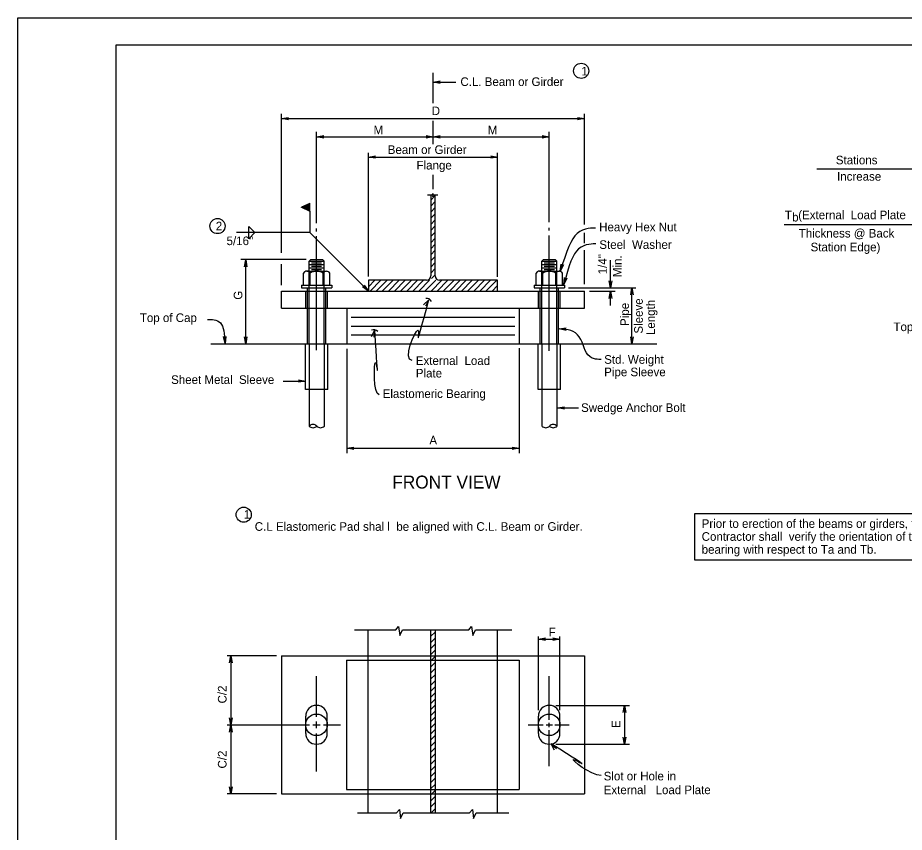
# Model space of a CAD drawing. Extents: x 113 to 232, y -103 to -27.
# Drawn here: x 115.25 to 123.82, y -54.27 to -46.39 of the extents above; entities that cross this region are included whole.
import ezdxf

# ---------------------------------------------------------------- set-up
doc = ezdxf.new("R2010")
doc.units = 0
for name, color, linetype in [('1', 7, 'Continuous'), ('B_Border', 7, 'Continuous'), ('B_Dimension', 7, 'Continuous'), ('B_No_Plot', 7, 'Continuous')]:
    doc.layers.add(name, color=color, linetype=linetype)

msp = doc.modelspace()

# ---------------------------------------------------------------- linework, layer by layer
at = {"layer": '1'}
for p, q in [((119.2638, -47.219), (119.2638, -46.9267)), ((119.2638, -47.0179), (119.4812, -47.0179)), ((117.7967, -48.6674), (117.7967, -47.3251)), ((117.7967, -47.3697), (120.7267, -47.3697)), ((119.2638, -47.6169), (119.2638, -47.3899)), ((120.7267, -48.3947), (120.7267, -47.3251)), ((118.1367, -48.3815), (118.1367, -47.4974)), ((118.1367, -47.5465), (119.2638, -47.5465)), ((119.2638, -47.5465), (120.3867, -47.5465)), ((120.3867, -48.3708), (120.3867, -47.4965)), ((118.6367, -48.8964), (118.6367, -47.7017)), ((118.6367, -47.7412), (119.8881, -47.7412)), ((119.8867, -48.8988), (119.8867, -47.7017)), ((119.2638, -48.0528), (119.2638, -47.9124)), ((122.9723, -47.8557), (124.0302, -47.8557)), ((119.21, -48.1072), (119.2535, -48.1072)), ((119.2409, -48.1072), (119.2409, -48.8915)), ((119.2535, -48.1072), (119.2614, -48.0931)), ((119.2614, -48.0931), (119.2614, -48.1262)), ((119.2614, -48.1262), (119.2676, -48.1072)), ((119.2676, -48.1072), (119.3079, -48.1072)), ((119.2824, -48.8915), (119.2824, -48.1072)), ((118.0711, -48.1895), (117.9901, -48.2273)), ((117.9901, -48.2273), (118.0711, -48.265)), ((118.0711, -48.1895), (118.0711, -48.1889)), ((118.0711, -48.265), (118.0711, -48.1895)), ((118.0711, -48.265), (118.0711, -48.2955)), ((118.0711, -48.2955), (118.0711, -48.4717)), ((117.4812, -48.5307), (117.4812, -48.4127)), ((117.4812, -48.4127), (117.5402, -48.4717)), ((118.1367, -48.46), (118.1367, -48.4325)), ((120.3867, -48.4531), (120.3867, -48.4257)), ((122.6575, -48.3931), (124.0554, -48.3931)), ((118.0711, -48.4717), (117.3619, -48.4717)), ((117.5402, -48.4717), (117.4812, -48.5307)), ((118.6367, -49.0373), (118.0711, -48.4717)), ((118.1367, -49.6095), (118.1367, -48.5071)), ((120.3867, -49.6144), (120.3867, -48.5002)), ((120.7267, -48.5731), (120.7267, -48.4734)), ((120.7267, -48.97), (120.7267, -48.6414)), ((118.0361, -48.7319), (117.4048, -48.7319)), ((117.4509, -49.5478), (117.4509, -48.7355)), ((117.7967, -48.9818), (117.7967, -48.7758)), ((118.0801, -48.7319), (118.0637, -48.7482)), ((118.0637, -48.8454), (118.0637, -48.7482)), ((118.0637, -48.7482), (118.2096, -48.7482)), ((118.0801, -48.7319), (118.1932, -48.7319)), ((118.0881, -48.7645), (118.1852, -48.7645)), ((118.1932, -48.7319), (118.2096, -48.7482)), ((118.2096, -48.8454), (118.2096, -48.7482)), ((120.3137, -48.7482), (120.3301, -48.7319)), ((120.3137, -48.7482), (120.4596, -48.7482)), ((120.3137, -48.8454), (120.3137, -48.7482)), ((120.3137, -48.7482), (120.4596, -48.7482)), ((120.3301, -48.7319), (120.4432, -48.7319)), ((120.3381, -48.7645), (120.4352, -48.7645)), ((120.4432, -48.7319), (120.4596, -48.7482)), ((120.4596, -48.8454), (120.4596, -48.7482)), ((120.978, -49.0064), (120.978, -48.7374)), ((118.0414, -48.8454), (118.2322, -48.8454)), ((118.0637, -48.7806), (118.2096, -48.7806)), ((118.0637, -48.813), (118.2096, -48.813)), ((118.0637, -49.5478), (118.0637, -48.8454)), ((118.0881, -48.797), (118.1852, -48.797)), ((118.0881, -48.8293), (118.1852, -48.8293)), ((118.2096, -49.5478), (118.2096, -48.8454)), ((120.2914, -48.8454), (120.4822, -48.8454)), ((120.3137, -48.7806), (120.4596, -48.7806)), ((120.3137, -48.813), (120.4596, -48.813)), ((120.3137, -49.5478), (120.3137, -48.8454)), ((120.3381, -48.797), (120.4352, -48.797)), ((120.3381, -48.8293), (120.4352, -48.8293)), ((120.4596, -49.5478), (120.4596, -48.8454)), ((118.0093, -48.9792), (118.0093, -48.8637)), ((118.0737, -48.9792), (118.0737, -48.8637)), ((118.1998, -48.9792), (118.1998, -48.8637)), ((118.2644, -48.9792), (118.2644, -48.8637)), ((119.1992, -48.9331), (118.6367, -48.9331)), ((118.6367, -48.9331), (118.6367, -49.0373)), ((119.8867, -48.9331), (119.3241, -48.9331)), ((119.8867, -49.0373), (119.8867, -48.9331)), ((120.2593, -48.9792), (120.2593, -48.8637)), ((120.3237, -48.9792), (120.3237, -48.8637)), ((120.4498, -48.9792), (120.4498, -48.8637)), ((120.5144, -48.9792), (120.5144, -48.8637)), ((117.9908, -48.9792), (118.2825, -48.9792)), ((117.9908, -48.9792), (117.9908, -49.0052)), ((117.9908, -49.0052), (118.2825, -49.0052)), ((118.0482, -49.0385), (118.0482, -49.0055)), ((118.2252, -49.0385), (118.2252, -49.0055)), ((118.2825, -48.9792), (118.2825, -49.0052)), ((120.2408, -48.9792), (120.5325, -48.9792)), ((120.2408, -48.9792), (120.2408, -49.0052)), ((120.2408, -49.0052), (120.5325, -49.0052)), ((120.2982, -49.0381), (120.2982, -49.0048)), ((120.4752, -49.0381), (120.4752, -49.0058)), ((120.5325, -48.9792), (120.5325, -49.0052)), ((120.5724, -49.0052), (121.2237, -49.0052)), ((121.1859, -49.5478), (121.1859, -49.0052)), ((117.7967, -49.204), (117.7967, -49.0373)), ((117.7967, -49.0373), (120.7267, -49.0373)), ((118.0326, -49.204), (118.0326, -49.0385)), ((118.0482, -49.204), (118.0482, -49.0385)), ((118.2252, -49.2038), (118.2252, -49.0385)), ((118.2407, -49.204), (118.2407, -49.0385)), ((120.2826, -49.2049), (120.2826, -49.0381)), ((120.2982, -49.2049), (120.2982, -49.0381)), ((120.4752, -49.2059), (120.4752, -49.0411)), ((120.4907, -49.2059), (120.4907, -49.0411)), ((120.7267, -49.204), (120.7267, -49.0373)), ((120.7745, -49.0373), (121.0236, -49.0373)), ((120.978, -49.1773), (120.978, -49.0397)), ((117.7967, -49.204), (120.7267, -49.204)), ((118.0482, -49.5478), (118.0482, -49.204)), ((118.2252, -49.5478), (118.2252, -49.2038)), ((118.4283, -49.204), (118.4283, -49.5478)), ((120.095, -49.204), (120.095, -49.5478)), ((118.47, -49.29), (120.0533, -49.29)), ((120.2982, -49.5478), (120.2982, -49.2049)), ((120.4752, -49.5478), (120.4752, -49.2059)), ((118.47, -49.376), (120.0533, -49.376)), ((118.47, -49.4619), (120.0533, -49.4619)), ((117.1126, -49.5478), (121.4253, -49.5478)), ((118.0282, -49.988), (118.0282, -49.5478)), ((118.0637, -49.5478), (118.0637, -49.988)), ((118.2096, -49.5478), (118.2096, -49.988)), ((118.2452, -49.988), (118.2452, -49.5478)), ((118.4283, -49.5953), (118.4283, -50.6057)), ((120.095, -49.5908), (120.095, -50.6057)), ((120.2782, -49.988), (120.2782, -49.5478)), ((120.3137, -49.5478), (120.3137, -49.988)), ((120.4596, -49.5478), (120.4596, -49.988)), ((120.4952, -49.988), (120.4952, -49.5478)), ((117.8138, -49.9073), (118.0297, -49.9073)), ((118.2452, -49.988), (118.0282, -49.988)), ((118.0637, -49.988), (118.0637, -50.3446)), ((118.2096, -49.988), (118.2096, -50.3445)), ((120.4952, -49.988), (120.2782, -49.988)), ((120.3137, -49.988), (120.3137, -50.3411)), ((120.4596, -49.988), (120.4596, -50.3413)), ((120.4665, -50.1678), (120.6692, -50.1678)), ((118.4283, -50.558), (120.095, -50.558)), ((118.502, -52.3141), (118.9014, -52.3141)), ((118.6354, -54.0829), (118.6354, -52.3141)), ((118.966, -52.3141), (119.6076, -52.3141)), ((119.2396, -54.0829), (119.2396, -52.3141)), ((119.2812, -52.3141), (119.2812, -54.0829)), ((119.6722, -52.3141), (120.0232, -52.3141)), ((119.8854, -54.0829), (119.8854, -52.3141)), ((120.2812, -53.0901), (120.2812, -52.3775)), ((120.2812, -52.4036), (120.4896, -52.4036)), ((120.4896, -53.0901), (120.4896, -52.3775)), ((117.7475, -52.5653), (117.2701, -52.5653)), ((117.3072, -52.5653), (117.3072, -53.2335)), ((117.7954, -52.5653), (117.7954, -53.8986)), ((117.7954, -52.5653), (118.6328, -52.5653)), ((118.427, -52.607), (118.427, -53.857)), ((118.427, -52.607), (120.0938, -52.607)), ((118.6328, -52.5653), (119.8877, -52.5653)), ((119.8877, -52.5653), (120.7254, -52.5653)), ((120.0938, -52.607), (120.0938, -53.857)), ((120.7254, -52.5653), (120.7254, -53.8986)), ((118.1354, -53.1561), (118.1354, -52.7613)), ((120.3854, -53.184), (120.3854, -52.7613)), ((120.4492, -53.0445), (121.1627, -53.0445)), ((121.1142, -53.0445), (121.1142, -53.4195)), ((117.2701, -53.232), (118.068, -53.232)), ((117.3072, -53.2335), (117.3072, -53.8986)), ((118.0312, -53.3153), (118.0312, -53.1486)), ((118.0993, -53.232), (118.1707, -53.232)), ((118.1354, -53.2648), (118.1354, -53.2014)), ((118.2019, -53.232), (118.2396, -53.232)), ((118.2396, -53.3153), (118.2396, -53.1486)), ((118.2396, -53.232), (118.3665, -53.232)), ((120.1817, -53.232), (120.3258, -53.232)), ((120.2812, -53.3153), (120.2812, -53.1486)), ((120.3571, -53.232), (120.4162, -53.232)), ((120.3854, -53.2535), (120.3854, -53.2118)), ((120.4406, -53.232), (120.4896, -53.232)), ((120.4896, -53.3153), (120.4896, -53.1486)), ((120.4896, -53.232), (120.5795, -53.232)), ((118.1354, -53.6818), (118.1354, -53.316)), ((120.3854, -53.6329), (120.3854, -53.283)), ((120.4492, -53.4195), (121.1627, -53.4195)), ((117.7475, -53.8986), (117.2701, -53.8986)), ((117.7954, -53.8986), (118.6328, -53.8986)), ((118.427, -53.857), (120.0938, -53.857)), ((118.6328, -53.8986), (119.8842, -53.8986)), ((119.8842, -53.8986), (120.7254, -53.8986)), ((118.5302, -54.083), (118.9095, -54.083)), ((118.9741, -54.083), (119.6156, -54.083)), ((119.6802, -54.083), (119.9949, -54.083))]:
    msp.add_line(p, q, dxfattribs=at)
for points in [[(119.2461, -48.1506), (119.2772, -48.1194)], [(117.9911, -48.2277), (117.9911, -48.2269)], [(117.9953, -48.2298), (117.9953, -48.2249)], [(117.9997, -48.2318), (117.9997, -48.2229)], [(118.004, -48.2337), (118.004, -48.2209)], [(118.0082, -48.2357), (118.0082, -48.2189)], [(118.0126, -48.2377), (118.0126, -48.2169)], [(118.0169, -48.2398), (118.0169, -48.2149)], [(118.0212, -48.2418), (118.0212, -48.2129)], [(118.0255, -48.2437), (118.0255, -48.2109)], [(118.0298, -48.2457), (118.0298, -48.2089)], [(118.0341, -48.2477), (118.0341, -48.2069)], [(118.0384, -48.2498), (118.0384, -48.2049)], [(118.0427, -48.2518), (118.0427, -48.2028)], [(118.047, -48.2537), (118.047, -48.2008)], [(118.0513, -48.2557), (118.0513, -48.1988)], [(118.0556, -48.2577), (118.0556, -48.1968)], [(118.0599, -48.2598), (118.0599, -48.1949)], [(118.0642, -48.2618), (118.0642, -48.1928)], [(118.0685, -48.2637), (118.0685, -48.1908)], [(119.2461, -48.2095), (119.2772, -48.1784)], [(119.2461, -48.2685), (119.2772, -48.2373)], [(119.2461, -48.3274), (119.2772, -48.2962)], [(119.2461, -48.3863), (119.2772, -48.3551)], [(119.2461, -48.4452), (119.2772, -48.414)], [(119.2461, -48.5041), (119.2772, -48.473)], [(119.2461, -48.563), (119.2772, -48.5319)], [(119.2461, -48.622), (119.2772, -48.5908)], [(119.2461, -48.6809), (119.2772, -48.6497)], [(119.2461, -48.7398), (119.2772, -48.7086)], [(119.2461, -48.7987), (119.2772, -48.7675)], [(119.2461, -48.8576), (119.2772, -48.8265)], [(118.6367, -48.9957), (118.6992, -48.9331)], [(118.6367, -48.9368), (118.6403, -48.9331)], [(118.654, -49.0373), (118.7582, -48.9331)], [(118.7129, -49.0373), (118.8171, -48.9331)], [(118.7718, -49.0373), (118.876, -48.9331)], [(118.8307, -49.0373), (118.9349, -48.9331)], [(118.8897, -49.0373), (118.9938, -48.9331)], [(118.9486, -49.0373), (119.0527, -48.9331)], [(119.0075, -49.0373), (119.1117, -48.9331)], [(119.0664, -49.0373), (119.1707, -48.9331)], [(119.1253, -49.0373), (119.2296, -48.9331)], [(119.1843, -49.0373), (119.2885, -48.9331)], [(119.2432, -49.0373), (119.3474, -48.9331)], [(119.2461, -48.9165), (119.2772, -48.8854)], [(119.3022, -49.0373), (119.4063, -48.9331)], [(119.3611, -49.0373), (119.4652, -48.9331)], [(119.42, -49.0373), (119.5242, -48.9331)], [(119.4789, -49.0373), (119.5832, -48.933)], [(119.5378, -49.0373), (119.642, -48.9331)], [(119.5968, -49.0372), (119.7009, -48.9331)], [(119.6557, -49.0373), (119.7599, -48.9331)], [(119.7147, -49.0373), (119.8188, -48.9331)], [(119.7736, -49.0373), (119.8777, -48.9331)], [(119.8325, -49.0373), (119.8867, -48.9831)], [(118.1474, -49.0373), (118.1474, -49.0373)], [(118.2652, -49.0373), (118.2652, -49.0373)], [(118.3242, -49.0373), (118.3242, -49.0373)], [(120.2801, -49.0373), (120.2801, -49.0373)], [(118.9014, -52.3141), (118.9287, -52.2816), (118.9408, -52.3684), (118.966, -52.3141)], [(119.6076, -52.3141), (119.6349, -52.2816), (119.647, -52.3684), (119.6722, -52.3141)], [(119.2396, -52.3761), (119.2812, -52.3345)], [(119.2396, -52.435), (119.2812, -52.3935)], [(119.2396, -52.494), (119.2812, -52.4524)], [(119.2396, -52.553), (119.2812, -52.5113)], [(119.2396, -52.6119), (119.2812, -52.5703)], [(119.2396, -52.6708), (119.2812, -52.6292)], [(119.2396, -52.7297), (119.2812, -52.6881)], [(119.2396, -52.7886), (119.2812, -52.747)], [(119.2396, -52.8475), (119.2812, -52.806)], [(119.2396, -52.9065), (119.2812, -52.8649)], [(119.2396, -52.9654), (119.2812, -52.9238)], [(119.2396, -53.0244), (119.2812, -52.9827)], [(119.2396, -53.0833), (119.2812, -53.0417)], [(119.2396, -53.1422), (119.2812, -53.1006)], [(119.2396, -53.2011), (119.2812, -53.1595)], [(119.2396, -53.26), (119.2812, -53.2185)], [(119.2396, -53.319), (119.2812, -53.2774)], [(119.2396, -53.3779), (119.2812, -53.3363)], [(119.2396, -53.4368), (119.2812, -53.3952)], [(119.2396, -53.4957), (119.2812, -53.4541)], [(119.2396, -53.5547), (119.2812, -53.513)], [(119.2396, -53.6136), (119.2812, -53.572)], [(119.2396, -53.6725), (119.2812, -53.631)], [(119.2396, -53.7315), (119.2812, -53.6899)], [(119.2396, -53.7904), (119.2812, -53.7488)], [(119.2396, -53.8493), (119.2812, -53.8077)], [(119.2396, -53.9082), (119.2812, -53.8666)], [(119.2396, -53.9671), (119.2812, -53.9255)], [(119.2396, -54.026), (119.2812, -53.9845)], [(118.9095, -54.083), (118.9368, -54.0505), (118.9489, -54.1372), (118.9741, -54.083)], [(119.2396, -54.085), (119.2812, -54.0434)], [(119.6156, -54.083), (119.6429, -54.0505), (119.655, -54.1372), (119.6802, -54.083)]]:
    msp.add_lwpolyline(points, dxfattribs=at)
msp.add_lwpolyline([(121.795, -51.1885), (124.7359, -51.1885), (124.7359, -51.6395), (121.795, -51.6395)], close=True, dxfattribs=at)
for centre, radius in [((120.6951, -46.9082), 0.0733), ((117.1785, -48.4089), 0.0733), ((117.4315, -51.2001), 0.0733), ((118.1354, -53.232), 0.1042), ((120.3854, -53.232), 0.1042)]:
    msp.add_circle(centre, radius, dxfattribs=at)
for centre, radius, start, end in [((118.0415, -48.8828), 0.0375, 30.80861, 149.1914), ((118.1368, -48.9634), 0.118, 57.68982, 122.31018), ((118.2322, -48.883), 0.0376, 30.95728, 149.04272), ((120.2915, -48.8828), 0.0375, 30.80861, 149.1914), ((120.3868, -48.9634), 0.118, 57.68982, 122.31018), ((120.4822, -48.883), 0.0376, 30.95728, 149.04272), ((119.1993, -48.8914), 0.0417, 270, 360), ((119.3241, -48.8914), 0.0417, 180, 270), ((119.2003, -49.1588), 0.0513, 21.6992, 99.92259), ((118.6902, -49.4617), 0.0513, 40.39617, 118.61956), ((118.1018, -50.3777), 0.0504, 43.71346, 136.28654), ((118.1018, -50.308), 0.0504, 223.71346, 316.28654), ((118.1747, -50.308), 0.0504, 223.71346, 316.28654), ((120.3518, -50.308), 0.0504, 223.71346, 316.28654), ((120.4247, -50.3777), 0.0504, 43.71346, 136.28654), ((120.4247, -50.308), 0.0504, 223.71346, 316.28654), ((118.1354, -53.1486), 0.1042, 0, 180), ((120.3854, -53.1486), 0.1042, 0, 180), ((118.1354, -53.3153), 0.1042, 180, 0), ((120.3854, -53.3153), 0.1042, 180, 0)]:
    msp.add_arc(centre, radius, start, end, dxfattribs=at)
for points in [[(120.8316, -48.4281), (120.8149, -48.4275), (120.6277, -48.4246), (120.5569, -48.6446), (120.4924, -48.8453)], [(120.8348, -48.5821), (120.8184, -48.5814), (120.6411, -48.5748), (120.58, -48.7839), (120.5256, -48.9755)], [(119.0616, -49.7082), (118.9597, -49.7082), (119.222, -49.1225), (119.0616, -49.7082), (119.222, -49.1225)], [(117.082, -49.3134), (117.1174, -49.3107), (117.2314, -49.3113), (117.2443, -49.4479), (117.2533, -49.5445)], [(118.7412, -50.0403), (118.683, -50.0369), (118.6995, -49.4157), (118.7412, -50.0403), (118.6995, -49.4157)], [(120.8864, -49.6981), (120.8695, -49.6993), (120.7319, -49.7054), (120.697, -49.4128), (120.5265, -49.4055), (120.4813, -49.4036)], [(120.8884, -53.7222), (120.7805, -53.7192), (120.4052, -53.4156), (120.8884, -53.7222), (120.4052, -53.4156)]]:
    msp.add_open_spline(points, degree=3, dxfattribs=at)
at = {"layer": 'B_Border'}
for p, q in [((116.1981, -46.6578), (137.2748, -46.6578)), ((116.1981, -60.3545), (116.1981, -46.6578)), ((116.1988, -60.3538), (116.1988, -46.6578))]:
    msp.add_line(p, q, dxfattribs=at)
at = {"layer": 'B_Dimension'}
for points in [[(119.3322, -47.0299), (119.2638, -47.0179), (119.3322, -47.0058)], [(117.865, -47.3818), (117.7967, -47.3697), (117.865, -47.3577)], [(120.6583, -47.3577), (120.7267, -47.3697), (120.6583, -47.3818)], [(118.205, -47.5585), (118.1367, -47.5465), (118.205, -47.5345)], [(119.1955, -47.5345), (119.2638, -47.5465), (119.1955, -47.5585)], [(119.3322, -47.5585), (119.2638, -47.5465), (119.3322, -47.5345)], [(120.3183, -47.5345), (120.3867, -47.5465), (120.3183, -47.5585)], [(118.705, -47.7532), (118.6367, -47.7412), (118.705, -47.7291)], [(119.8198, -47.7291), (119.8881, -47.7412), (119.8198, -47.7532)], [(117.4389, -48.8038), (117.4509, -48.7355), (117.463, -48.8038)], [(120.5247, -48.784), (120.4924, -48.8453), (120.5018, -48.7766)], [(120.5558, -48.9131), (120.5256, -48.9755), (120.5327, -48.9065)], [(120.99, -48.938), (120.978, -49.0064), (120.966, -48.938)], [(118.5969, -48.9805), (118.6367, -49.0373), (118.5798, -48.9975)], [(121.1739, -49.0735), (121.1859, -49.0052), (121.198, -49.0735)], [(120.966, -49.108), (120.978, -49.0397), (120.99, -49.108)], [(119.1705, -49.169), (119.222, -49.1225), (119.1895, -49.1838)], [(118.6657, -49.4763), (118.6995, -49.4157), (118.6885, -49.4842)], [(120.549, -49.4186), (120.4813, -49.4036), (120.5501, -49.3945)], [(117.2589, -49.4754), (117.2533, -49.5445), (117.235, -49.4776)], [(117.463, -49.4795), (117.4509, -49.5478), (117.4389, -49.4795)], [(121.198, -49.4795), (121.1859, -49.5478), (121.1739, -49.4795)], [(117.9614, -49.8953), (118.0297, -49.9073), (117.9614, -49.9194)], [(120.5348, -50.1798), (120.4665, -50.1678), (120.5348, -50.1558)], [(118.4966, -50.5701), (118.4283, -50.558), (118.4966, -50.546)], [(120.0267, -50.546), (120.095, -50.558), (120.0267, -50.5701)], [(120.3496, -52.4157), (120.2812, -52.4036), (120.3496, -52.3916)], [(120.4213, -52.3916), (120.4896, -52.4036), (120.4213, -52.4157)], [(117.2951, -52.6336), (117.3072, -52.5653), (117.3192, -52.6336)], [(121.1022, -53.1128), (121.1142, -53.0445), (121.1263, -53.1128)], [(117.3192, -53.1652), (117.3072, -53.2335), (117.2951, -53.1652)], [(117.2951, -53.3019), (117.3072, -53.2335), (117.3192, -53.3019)], [(121.1263, -53.3511), (121.1142, -53.4195), (121.1022, -53.3511)], [(120.4379, -53.4768), (120.4052, -53.4156), (120.4569, -53.4619)], [(117.3192, -53.8303), (117.3072, -53.8986), (117.2951, -53.8303)]]:
    msp.add_lwpolyline(points, dxfattribs=at)
at = {"layer": 'B_No_Plot'}
msp.add_lwpolyline([(115.2465, -46.3942), (137.5798, -46.3942), (137.5798, -60.6182), (115.2465, -60.6182)], close=True, dxfattribs=at)

# ---------------------------------------------------------------- texts
at = {"layer": '1'}
for s, height, p in [('1', 0.0833, (120.6961, -46.9527)), ('C.L. Beam or Girder', 0.083334, (119.5269, -47.0544)), ('D', 0.0833, (119.2493, -47.3362)), ('M', 0.0833, (118.6872, -47.5214)), ('M', 0.0833, (119.7912, -47.5214)), ('Beam or Girder', 0.083334, (118.8246, -47.7118)), ('Stations', 0.08333, (123.157, -47.8119)), ('Flange', 0.08333, (119.1026, -47.8617)), ('Increase', 0.08333, (123.1686, -47.9702)), ('T  (External  Load Plate', 0.083334, (122.6635, -48.3428)), ('b', 0.0833, (122.7343, -48.3646)), ('2', 0.0833, (117.1617, -48.45)), ('Heavy Hex Nut', 0.083334, (120.8687, -48.4596)), ('Thickness @ Back', 0.083334, (122.7982, -48.5197)), ("5/16''", 0.08333, (117.266, -48.5931)), ('Steel  Washer', 0.083334, (120.8702, -48.6297)), ('Station Edge)', 0.083334, (122.9125, -48.6531)), ('Top of Cap', 0.08333, (116.4273, -49.3369)), ('Top of Cap', 0.08333, (123.7143, -49.4248)), ('External  Load ', 0.083334, (119.0957, -49.7521)), ('Std. Weight ', 0.083334, (120.9171, -49.7405)), ('Plate', 0.08333, (119.0957, -49.8729)), ('Pipe Sleeve', 0.083334, (120.9171, -49.8613)), ('Sheet Metal  Sleeve', 0.083334, (116.7296, -49.9357)), ('Elastomeric Bearing', 0.083334, (118.7754, -50.0711)), ('Swedge Anchor Bolt', 0.083334, (120.6938, -50.2064)), ('A', 0.0833, (119.2269, -50.5205)), ('FRONT VIEW', 0.12483, (118.8677, -50.9468)), ('1', 0.0833, (117.4325, -51.2387)), ('Prior to erection of the beams or girders, the ', 0.083334, (121.8598, -51.3276)), ('C.L Elastomeric Pad shal l  be aligned with C.L. Beam or Girder.', 0.083334, (117.5384, -51.3559)), ('Contractor shall  verify the orientation of the ', 0.083334, (121.8598, -51.4526)), ('bearing with respect to Ta and Tb.', 0.083334, (121.8598, -51.5776)), ('F', 0.0833, (120.3801, -52.3765)), ('Slot or Hole in', 0.083334, (120.9123, -53.7693)), ('External   Load Plate', 0.083334, (120.9123, -53.9026))]:
    msp.add_text(s, height=height, dxfattribs=at).set_placement(p)
for s, height, p in [("1/4''", 0.08333, (120.9426, -48.8758)), ('Min.', 0.08333, (121.085, -48.9027)), ('G', 0.0833, (117.4183, -49.1207)), ('Sleeve ', 0.08333, (121.2903, -49.4485)), ('Pipe', 0.08333, (121.1564, -49.3743)), ('Length', 0.08333, (121.4079, -49.4631)), ('C/2', 0.08333, (117.2655, -53.0253)), ('E', 0.0833, (121.0726, -53.2633)), ('C/2', 0.08333, (117.2655, -53.6545))]:
    msp.add_text(s, height=height, rotation=90, dxfattribs=at).set_placement(p)

doc.saveas('drawing.dxf')
